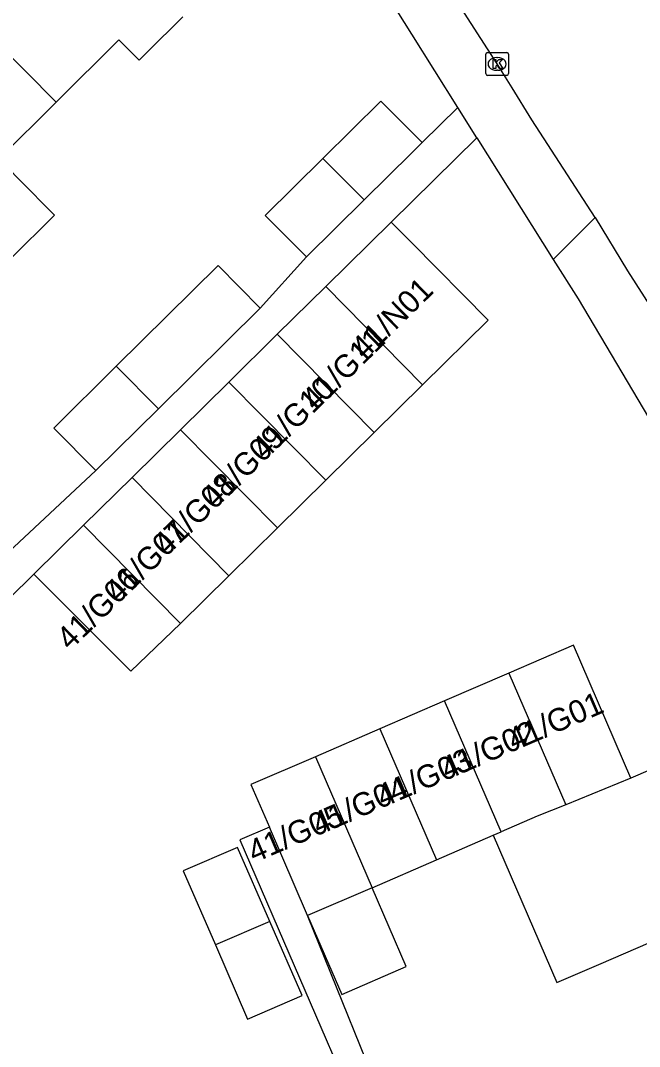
# Model space of a CAD drawing. Extents: x 159353 to 160616, y 385893 to 387321.
# Drawn here: x 159482.82 to 159510, y 386342.13 to 386387.21 of the extents above; entities that cross this region are included whole.
import ezdxf

# ---------------------------------------------------------------- set-up
doc = ezdxf.new("R2010")
doc.units = 0
for name, color, linetype in [('IMGEO_Kolk', 7, 'Continuous'), ('IMGEO_Pand', 7, 'Continuous'), ('IMGEO_Pand_nummerreeks', 7, 'Continuous'), ('IMGEO_Rijbaan_lokaal_gesloten', 7, 'Continuous'), ('IMGEO_Voetpad_open', 7, 'Continuous')]:
    doc.layers.add(name, color=color, linetype=linetype)

msp = doc.modelspace()

# ---------------------------------------------------------------- linework, layer by layer
at = {"layer": 'IMGEO_Kolk'}
for p, q in [((159503.249, 386384.88), (159503.249, 386385.732)), ((159503.324, 386385.806), (159504.176, 386385.806)), ((159503.737, 386385.586), (159503.762, 386385.586)), ((159504.25, 386385.732), (159504.25, 386384.88)), ((159503.76, 386385.026), (159503.735, 386385.026)), ((159504.176, 386384.806), (159503.324, 386384.806))]:
    msp.add_line(p, q, dxfattribs=at)
for points in [[(159503.249, 386384.88), (159503.249, 386385.732)], [(159503.324, 386385.806), (159504.176, 386385.806)], [(159503.57, 386385.506), (159503.693, 386385.506), (159503.693, 386385.355), (159503.823, 386385.506), (159503.987, 386385.506), (159503.841, 386385.355), (159503.994, 386385.106), (159503.842, 386385.106), (159503.757, 386385.27), (159503.693, 386385.203), (159503.693, 386385.106), (159503.57, 386385.106), (159503.57, 386385.506)], [(159504.25, 386385.732), (159504.25, 386384.88)], [(159504.176, 386384.806), (159503.324, 386384.806)]]:
    msp.add_lwpolyline(points, dxfattribs=at)
for centre, start, end in [((159503.326, 386385.73), 91.552, 178.448), ((159503.326, 386385.73), 91.552, 178.448), ((159504.174, 386385.73), 1.552, 88.448), ((159504.174, 386385.73), 1.552, 88.448), ((159503.326, 386384.882), 181.552, 268.448), ((159503.326, 386384.882), 181.552, 268.448), ((159504.174, 386384.882), 271.552, 358.448), ((159504.174, 386384.882), 271.552, 358.448)]:
    msp.add_arc(centre, 0.0765, start, end, dxfattribs=at)
for centre, major_axis, ratio, start_param, end_param in [((159503.736, 386385.306), (-0.387, 0.002), 0.722429, 4.712389, 7.853982), ((159503.761, 386385.306), (-0.39, 0.002), 0.717154, 1.570796, 4.712389)]:
    msp.add_ellipse(centre, major_axis=major_axis, ratio=ratio, start_param=start_param, end_param=end_param, dxfattribs=at)
at = {"layer": 'IMGEO_Pand'}
for points in [[(159477.614, 386390.462), (159484.376, 386383.633)], [(159489.945, 386387.372), (159488.364, 386385.807), (159488.028, 386385.474), (159487.141, 386386.37), (159484.376, 386383.633)], [(159484.376, 386383.633), (159481.858, 386381.14), (159482.746, 386380.245), (159484.308, 386378.668), (159482.356, 386376.735), (159480.793, 386378.313)], [(159496.098, 386381.159), (159498.642, 386383.677), (159500, 386382.305), (159500.45, 386381.85)], [(159500.45, 386381.85), (159500, 386381.405), (159497.907, 386379.332)], [(159495.376, 386376.827), (159493.568, 386378.654), (159496.098, 386381.159)], [(159497.907, 386379.332), (159496.098, 386381.159)], [(159497.907, 386379.332), (159495.376, 386376.827)], [(159499.095, 386378.359), (159496.22, 386375.523)], [(159500.475, 386371.208), (159503.35, 386374.044), (159500, 386377.441), (159499.095, 386378.359)], [(159487.022, 386372.023), (159491.491, 386376.45), (159493.341, 386374.582)], [(159496.22, 386375.523), (159494.094, 386373.426)], [(159500.475, 386371.208), (159496.22, 386375.523)], [(159493.341, 386374.582), (159488.872, 386370.156)], [(159494.094, 386373.426), (159491.967, 386371.329)], [(159494.094, 386373.426), (159498.348, 386369.111)], [(159486.129, 386367.439), (159484.279, 386369.307), (159487.022, 386372.023)], [(159488.872, 386370.156), (159487.022, 386372.023)], [(159491.967, 386371.329), (159489.841, 386369.233)], [(159496.222, 386367.014), (159491.967, 386371.329)], [(159498.348, 386369.111), (159500.475, 386371.208)], [(159488.872, 386370.156), (159486.129, 386367.439)], [(159487.714, 386367.136), (159489.841, 386369.233)], [(159489.841, 386369.233), (159494.096, 386364.918)], [(159496.222, 386367.014), (159498.348, 386369.111)], [(159485.588, 386365.039), (159487.714, 386367.136)], [(159491.969, 386362.821), (159487.714, 386367.136)], [(159494.096, 386364.918), (159496.222, 386367.014)], [(159485.588, 386365.039), (159483.403, 386362.885)], [(159489.842, 386360.724), (159485.588, 386365.039)], [(159491.969, 386362.821), (159494.096, 386364.918)], [(159483.403, 386362.885), (159487.667, 386358.631), (159489.842, 386360.724)], [(159489.842, 386360.724), (159491.969, 386362.821)], [(159509.625, 386353.922), (159507.098, 386359.765), (159504.266, 386358.54)], [(159504.266, 386358.54), (159501.434, 386357.316)], [(159504.266, 386358.54), (159506.767, 386352.758)], [(159501.434, 386357.316), (159498.603, 386356.091)], [(159503.923, 386351.561), (159501.434, 386357.316)], [(159498.603, 386356.091), (159495.771, 386354.867)], [(159498.603, 386356.091), (159501.091, 386350.336)], [(159516.633, 386349.372), (159513.871, 386355.758), (159509.625, 386353.922)], [(159495.771, 386354.867), (159492.939, 386353.642), (159493.746, 386351.775)], [(159495.771, 386354.867), (159498.26, 386349.111)], [(159509.625, 386353.922), (159506.767, 386352.758)], [(159506.767, 386352.758), (159505.515, 386352.249), (159503.923, 386351.561)], [(159495.428, 386347.887), (159493.746, 386351.775)], [(159501.091, 386350.336), (159503.581, 386351.413)], [(159503.581, 386351.413), (159503.923, 386351.561)], [(159503.581, 386351.413), (159506.377, 386344.942), (159508.32, 386345.781), (159510.387, 386346.674)], [(159493.76, 386347.628), (159492.341, 386350.879), (159489.967, 386349.853), (159491.375, 386346.597)], [(159498.26, 386349.111), (159501.091, 386350.336)], [(159498.26, 386349.111), (159495.428, 386347.887)], [(159495.428, 386347.887), (159496.929, 386344.417), (159499.76, 386345.641), (159498.26, 386349.111)], [(159493.76, 386347.628), (159491.375, 386346.597)], [(159491.375, 386346.597), (159492.783, 386343.341), (159495.18, 386344.377), (159493.76, 386347.628)]]:
    msp.add_lwpolyline(points, dxfattribs=at)
at = {"layer": 'IMGEO_Rijbaan_lokaal_gesloten'}
for points in [[(159508.049, 386378.563), (159505.275, 386382.845), (159504.404, 386384.253), (159503.75, 386385.306), (159491.908, 386403.706)], [(159508.049, 386378.563), (159509.479, 386376.213), (159510.58, 386374.496), (159511.352, 386373.226), (159512.473, 386371.498), (159513.621, 386369.485)]]:
    msp.add_lwpolyline(points, dxfattribs=at)
at = {"layer": 'IMGEO_Voetpad_open'}
for points in [[(159502.017, 386383.4), (159500, 386386.614), (159489.438, 386403.44)], [(159500.45, 386381.85), (159502.017, 386383.4)], [(159502.854, 386382.067), (159502.017, 386383.4)], [(159499.095, 386378.359), (159502.854, 386382.067)], [(159502.854, 386382.067), (159506.211, 386376.719)], [(159506.211, 386376.719), (159508.049, 386378.563)], [(159493.341, 386374.582), (159495.376, 386376.827)], [(159506.211, 386376.719), (159507.312, 386374.992), (159511.384, 386368.121)], [(159482.083, 386363.664), (159486.129, 386367.439)], [(159458.454, 386342.171), (159469.132, 386348.816), (159483.403, 386362.885)], [(159493.746, 386351.775), (159492.454, 386351.216), (159497.696, 386339.084)], [(159499.27, 386338.371), (159495.428, 386347.887)]]:
    msp.add_lwpolyline(points, dxfattribs=at)

# ---------------------------------------------------------------- texts
at = {"layer": 'IMGEO_Pand_nummerreeks'}
for s, rotation, p in [('41/N01', 44.3839, (159497.937, 386372.275)), ('41/G11', 44.3312, (159495.762, 386370.023)), ('41/G10', 44.3312, (159493.56, 386367.872)), ('41/G09', 44.3312, (159491.365, 386365.728)), ('41/G08', 44.3312, (159489.245, 386363.656)), ('41/G07', 44.3312, (159487.117, 386361.578)), ('41/G06', 44.3312, (159484.992, 386359.501)), ('41/G01', 23.327, (159504.485, 386355.105)), ('41/G02', 23.327, (159501.551, 386353.84)), ('41/G03', 23.3251, (159498.73, 386352.623)), ('41/G04', 23.327, (159495.903, 386351.404)), ('41/G05', 23.3251, (159493.076, 386350.185))]:
    msp.add_text(s, height=1, rotation=rotation, dxfattribs=at).set_placement(p)

doc.saveas('drawing.dxf')
